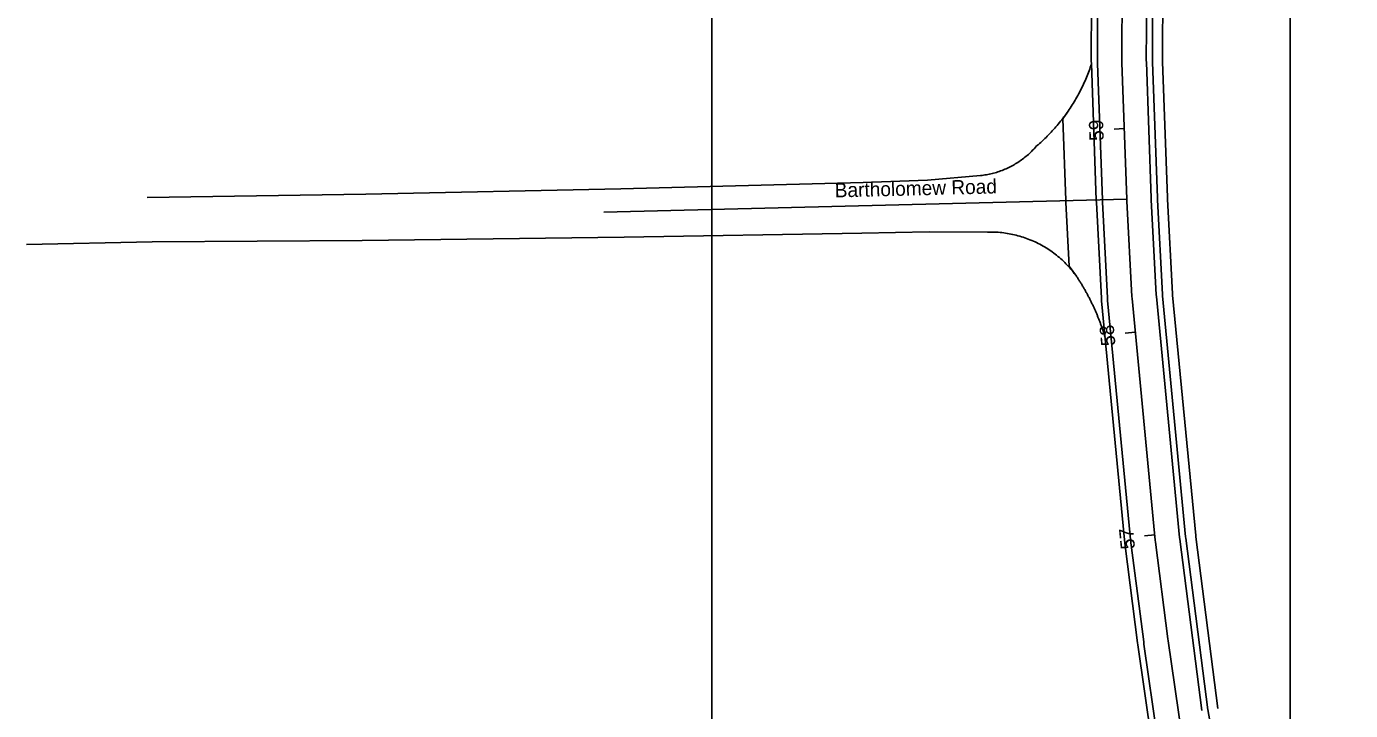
# Model space of a CAD drawing. Extents: x 2318076 to 2324211, y 613525 to 630327.
# Drawn here: x 2318076 to 2318726, y 620517 to 620852 of the extents above; entities that cross this region are included whole.
import ezdxf

# ---------------------------------------------------------------- set-up
doc = ezdxf.new("R2010")
doc.units = 0
for name, color, linetype in [('GE_P_CL_50', 7, 'Continuous'), ('GE_X_CL_50', 7, 'Continuous'), ('PV_P_EOP', 7, 'Continuous'), ('PV_P_Shoulder', 7, 'Continuous'), ('RD_X_GR_Rt', 7, 'Continuous'), ('RS_Raster1', 7, 'Continuous'), ('SC_Scratch3', 7, 'Continuous'), ('TX_P_1', 7, 'Continuous')]:
    doc.layers.add(name, color=color, linetype=linetype)

msp = doc.modelspace()

# ---------------------------------------------------------------- linework, layer by layer
at = {"layer": 'GE_P_CL_50'}
for p, q in [((2318615.25, 620802.3), (2318610.26, 620802.12)), ((2318620.66, 620702.47), (2318615.68, 620701.99)), ((2318630.24, 620602.93), (2318625.26, 620602.45))]:
    msp.add_line(p, q, dxfattribs=at)
msp.add_lwpolyline([(2318643.51, 620504.66), (2318636.81, 620551.04), (2318636.68, 620552.01), (2318630.59, 620599.46), (2318630.48, 620600.43), (2318619.07, 620719), (2318619.01, 620719.99), (2318616.54, 620766.75), (2318616.5, 620767.74), (2318614.09, 620834.59), (2318614.09, 620835.59), (2318614.08, 620836.59), (2318614.07, 620837.58), (2318614.09, 620849.48), (2318614.1, 620850.47), (2318614.18, 620857.38)], dxfattribs=at)
at = {"layer": 'GE_X_CL_50'}
msp.add_line((2318359.77, 620761.32), (2318616.5, 620767.74), dxfattribs=at)
at = {"layer": 'PV_P_EOP'}
for points in [[(2318631.64, 620502.89), (2318624.93, 620549.37), (2318624.78, 620550.44), (2318618.68, 620597.98), (2318618.54, 620599.14), (2318607.11, 620718.03), (2318607.03, 620719.28), (2318604.55, 620766.19), (2318604.51, 620767.29), (2318602.1, 620834.32), (2318602.09, 620835.48), (2318602.08, 620836.49), (2318602.07, 620837.55), (2318602.09, 620849.54), (2318602.1, 620850.59), (2318602.18, 620857.53)], [(2318653.3, 620516.78), (2318642.5, 620600.94), (2318642.41, 620601.72), (2318631.03, 620719.97), (2318630.99, 620720.7), (2318628.52, 620767.31), (2318628.49, 620768.2), (2318626.09, 620834.86), (2318626.08, 620835.69), (2318626.08, 620836.68), (2318626.07, 620837.62), (2318626.09, 620849.42), (2318626.1, 620850.35), (2318626.18, 620857.23)], [(2318599.11, 620833.88), (2318598.88, 620833.18), (2318598.59, 620832.34), (2318598.3, 620831.5), (2318597.99, 620830.66), (2318597.68, 620829.83), (2318597.36, 620828.99), (2318597.03, 620828.17), (2318596.69, 620827.34), (2318596.34, 620826.52), (2318595.99, 620825.7), (2318595.63, 620824.89), (2318595.25, 620824.08), (2318594.88, 620823.27), (2318594.49, 620822.47), (2318594.09, 620821.67), (2318593.69, 620820.87), (2318593.28, 620820.08), (2318592.86, 620819.29), (2318592.43, 620818.51), (2318592, 620817.73), (2318591.56, 620816.96), (2318591.11, 620816.19), (2318590.65, 620815.43), (2318590.18, 620814.67), (2318589.71, 620813.91), (2318589.23, 620813.16), (2318588.74, 620812.41), (2318588.24, 620811.67), (2318587.74, 620810.94), (2318585.07, 620807.12)], [(2318588.2, 620734.8), (2318586.55, 620766.05), (2318586.51, 620767.17), (2318585.07, 620807.12)], [(2318591.8, 620729.86), (2318588.2, 620734.8)], [(2318605.83, 620699.99), (2318605.72, 620700.35), (2318605.6, 620700.74), (2318605.48, 620701.12), (2318605.36, 620701.51), (2318605.24, 620701.89), (2318605.11, 620702.28), (2318604.99, 620702.66), (2318604.86, 620703.05), (2318604.73, 620703.43), (2318604.6, 620703.81), (2318604.47, 620704.2), (2318604.34, 620704.58), (2318604.21, 620704.96), (2318604.07, 620705.34), (2318603.94, 620705.72), (2318603.8, 620706.1), (2318603.66, 620706.48), (2318603.52, 620706.86), (2318603.38, 620707.24), (2318603.23, 620707.62), (2318603.09, 620707.99), (2318602.94, 620708.37), (2318602.8, 620708.75), (2318602.65, 620709.12), (2318602.5, 620709.5), (2318602.35, 620709.87), (2318602.19, 620710.25), (2318602.04, 620710.62), (2318601.89, 620711), (2318601.73, 620711.37), (2318601.57, 620711.74), (2318601.41, 620712.11), (2318601.25, 620712.48), (2318601.09, 620712.85), (2318600.93, 620713.22), (2318600.76, 620713.59), (2318600.6, 620713.96), (2318600.43, 620714.33), (2318600.26, 620714.7), (2318600.09, 620715.06), (2318599.92, 620715.43), (2318599.75, 620715.79), (2318599.57, 620716.16), (2318599.4, 620716.52), (2318599.22, 620716.89), (2318599.04, 620717.25), (2318598.86, 620717.61), (2318598.68, 620717.97), (2318598.5, 620718.34), (2318598.32, 620718.7), (2318598.14, 620719.06), (2318597.95, 620719.42), (2318597.76, 620719.77), (2318597.58, 620720.13), (2318597.39, 620720.49), (2318597.2, 620720.85), (2318597, 620721.2), (2318596.81, 620721.56), (2318596.62, 620721.91), (2318596.42, 620722.26), (2318596.22, 620722.62), (2318596.03, 620722.97), (2318595.83, 620723.32), (2318595.63, 620723.67), (2318595.42, 620724.02), (2318595.22, 620724.37), (2318595.02, 620724.72), (2318594.81, 620725.07), (2318594.6, 620725.42), (2318594.39, 620725.76), (2318594.19, 620726.11), (2318593.97, 620726.45), (2318593.76, 620726.8), (2318593.55, 620727.14), (2318593.33, 620727.48), (2318593.12, 620727.82), (2318592.9, 620728.17), (2318592.68, 620728.51), (2318592.47, 620728.85), (2318592.24, 620729.18), (2318592.02, 620729.52), (2318591.8, 620729.86)]]:
    msp.add_lwpolyline(points, dxfattribs=at)
at = {"layer": 'PV_P_Shoulder'}
for points in [[(2318628.67, 620502.45), (2318621.96, 620548.96), (2318621.81, 620550.04), (2318615.71, 620597.61), (2318615.56, 620598.82), (2318604.12, 620717.79), (2318604.03, 620719.11), (2318601.55, 620766.05), (2318601.51, 620767.17), (2318599.1, 620834.25), (2318599.09, 620835.45), (2318599.08, 620836.46), (2318599.07, 620837.54), (2318599.09, 620849.56), (2318599.1, 620850.62), (2318599.18, 620857.57)], [(2318656.27, 620517.16), (2318645.48, 620601.31), (2318645.39, 620602.05), (2318634.02, 620720.21), (2318633.98, 620720.88), (2318631.52, 620767.44), (2318631.49, 620768.31), (2318629.09, 620834.93), (2318629.08, 620835.72), (2318629.08, 620836.71), (2318629.07, 620837.63), (2318629.09, 620849.4), (2318629.1, 620850.32), (2318629.18, 620857.19)], [(2318726.31, 620118.23), (2318656.25, 620517.3)]]:
    msp.add_lwpolyline(points, dxfattribs=at)
at = {"layer": 'RD_X_GR_Rt'}
msp.add_lwpolyline([(2318661.23, 620517.8), (2318650.44, 620601.93), (2318650.36, 620602.58), (2318639.01, 620720.61), (2318638.97, 620721.17), (2318636.52, 620767.68), (2318636.48, 620768.5), (2318634.09, 620835.04), (2318634.08, 620835.77), (2318634.08, 620836.75), (2318634.07, 620837.64), (2318634.09, 620849.38), (2318634.1, 620850.27), (2318634.18, 620857.13)], dxfattribs=at)
at = {"layer": 'RS_Raster1'}
for p, q in [((2318544.73, 620779.28), (2318518.65, 620776.96)), ((2318369.82, 620749), (2318486.39, 620751.03)), ((2318486.39, 620751.03), (2318519.51, 620751.7)), ((2318548.09, 620751.54), (2318519.51, 620751.7))]:
    msp.add_line(p, q, dxfattribs=at)
for points in [[(2318599.11, 620833.88), (2318598.88, 620833.18), (2318598.59, 620832.34), (2318598.3, 620831.5), (2318597.99, 620830.66), (2318597.68, 620829.83), (2318597.36, 620828.99), (2318597.03, 620828.17), (2318596.69, 620827.34), (2318596.34, 620826.52), (2318595.99, 620825.7), (2318595.63, 620824.89), (2318595.25, 620824.08), (2318594.88, 620823.27), (2318594.49, 620822.47), (2318594.09, 620821.67), (2318593.69, 620820.87), (2318593.28, 620820.08), (2318592.86, 620819.29), (2318592.43, 620818.51), (2318592, 620817.73), (2318591.56, 620816.96), (2318591.11, 620816.19), (2318590.65, 620815.43), (2318590.18, 620814.67), (2318589.71, 620813.91), (2318589.23, 620813.16), (2318588.74, 620812.41), (2318588.24, 620811.67), (2318587.74, 620810.94), (2318587.23, 620810.21), (2318586.71, 620809.48), (2318586.19, 620808.76), (2318585.66, 620808.05), (2318585.12, 620807.34), (2318584.57, 620806.63), (2318584.02, 620805.94), (2318583.46, 620805.24), (2318582.89, 620804.56), (2318582.32, 620803.87), (2318581.74, 620803.2), (2318581.15, 620802.53), (2318580.55, 620801.87), (2318579.95, 620801.21), (2318579.35, 620800.56), (2318578.73, 620799.91), (2318578.11, 620799.27), (2318577.49, 620798.64), (2318576.85, 620798.01), (2318576.21, 620797.39), (2318575.57, 620796.78), (2318574.92, 620796.17), (2318574.26, 620795.57), (2318573.59, 620794.98), (2318572.93, 620794.39), (2318572.25, 620793.81)], [(2318572.25, 620793.81), (2318571.77, 620793.26), (2318571.29, 620792.72), (2318570.8, 620792.19), (2318570.29, 620791.67), (2318569.78, 620791.15), (2318569.26, 620790.65), (2318568.73, 620790.15), (2318568.2, 620789.67), (2318567.65, 620789.19), (2318567.1, 620788.72), (2318566.53, 620788.26), (2318565.96, 620787.81), (2318565.39, 620787.37), (2318564.8, 620786.95), (2318564.21, 620786.53), (2318563.61, 620786.12), (2318563.01, 620785.72), (2318562.39, 620785.33), (2318561.77, 620784.96), (2318561.15, 620784.59), (2318560.52, 620784.24), (2318559.88, 620783.89), (2318559.23, 620783.56), (2318558.58, 620783.24), (2318557.93, 620782.93), (2318557.27, 620782.63), (2318556.61, 620782.34), (2318555.94, 620782.07), (2318555.26, 620781.8), (2318554.58, 620781.55), (2318553.9, 620781.31), (2318553.21, 620781.08), (2318552.52, 620780.86), (2318551.83, 620780.66), (2318551.13, 620780.47), (2318550.43, 620780.28), (2318549.72, 620780.12), (2318549.02, 620779.96), (2318548.31, 620779.82), (2318547.6, 620779.68), (2318546.88, 620779.56), (2318546.17, 620779.46), (2318545.45, 620779.36), (2318544.73, 620779.28)], [(2318518.65, 620776.96), (2318487.18, 620775.88), (2318368.13, 620772.81)], [(2318591.8, 620729.86), (2318591.28, 620730.58), (2318590.74, 620731.29), (2318590.19, 620731.99), (2318589.63, 620732.69), (2318589.05, 620733.37), (2318588.47, 620734.04), (2318587.87, 620734.7), (2318587.27, 620735.36), (2318586.65, 620736), (2318586.02, 620736.63), (2318585.38, 620737.25), (2318584.73, 620737.86), (2318584.07, 620738.46), (2318583.4, 620739.04), (2318582.72, 620739.62), (2318582.02, 620740.18), (2318581.32, 620740.73), (2318580.61, 620741.27), (2318579.9, 620741.8), (2318579.17, 620742.31), (2318578.43, 620742.81), (2318577.69, 620743.3), (2318576.93, 620743.78), (2318576.17, 620744.24), (2318575.4, 620744.69), (2318574.62, 620745.13), (2318573.84, 620745.55), (2318573.05, 620745.96), (2318572.25, 620746.36), (2318571.45, 620746.74), (2318570.63, 620747.11), (2318569.82, 620747.46), (2318568.99, 620747.8), (2318568.16, 620748.13), (2318567.33, 620748.44), (2318566.49, 620748.74), (2318565.64, 620749.02), (2318564.79, 620749.29), (2318563.94, 620749.54), (2318563.08, 620749.78), (2318562.22, 620750), (2318561.35, 620750.21), (2318560.48, 620750.41), (2318559.61, 620750.59), (2318558.73, 620750.75), (2318557.86, 620750.9), (2318556.98, 620751.04), (2318556.09, 620751.15), (2318555.21, 620751.26), (2318554.32, 620751.35), (2318553.43, 620751.42), (2318552.54, 620751.48), (2318551.65, 620751.52), (2318550.76, 620751.55), (2318549.87, 620751.56), (2318548.98, 620751.56), (2318548.09, 620751.54)], [(2318605.83, 620699.99), (2318605.72, 620700.35), (2318605.6, 620700.74), (2318605.48, 620701.12), (2318605.36, 620701.51), (2318605.24, 620701.89), (2318605.11, 620702.28), (2318604.99, 620702.66), (2318604.86, 620703.05), (2318604.73, 620703.43), (2318604.6, 620703.81), (2318604.47, 620704.2), (2318604.34, 620704.58), (2318604.21, 620704.96), (2318604.07, 620705.34), (2318603.94, 620705.72), (2318603.8, 620706.1), (2318603.66, 620706.48), (2318603.52, 620706.86), (2318603.38, 620707.24), (2318603.23, 620707.62), (2318603.09, 620707.99), (2318602.94, 620708.37), (2318602.8, 620708.75), (2318602.65, 620709.12), (2318602.5, 620709.5), (2318602.35, 620709.87), (2318602.19, 620710.25), (2318602.04, 620710.62), (2318601.89, 620711), (2318601.73, 620711.37), (2318601.57, 620711.74), (2318601.41, 620712.11), (2318601.25, 620712.48), (2318601.09, 620712.85), (2318600.93, 620713.22), (2318600.76, 620713.59), (2318600.6, 620713.96), (2318600.43, 620714.33), (2318600.26, 620714.7), (2318600.09, 620715.06), (2318599.92, 620715.43), (2318599.75, 620715.79), (2318599.57, 620716.16), (2318599.4, 620716.52), (2318599.22, 620716.89), (2318599.04, 620717.25), (2318598.86, 620717.61), (2318598.68, 620717.97), (2318598.5, 620718.34), (2318598.32, 620718.7), (2318598.14, 620719.06), (2318597.95, 620719.42), (2318597.76, 620719.77), (2318597.58, 620720.13), (2318597.39, 620720.49), (2318597.2, 620720.85), (2318597, 620721.2), (2318596.81, 620721.56), (2318596.62, 620721.91), (2318596.42, 620722.26), (2318596.22, 620722.62), (2318596.03, 620722.97), (2318595.83, 620723.32), (2318595.63, 620723.67), (2318595.42, 620724.02), (2318595.22, 620724.37), (2318595.02, 620724.72), (2318594.81, 620725.07), (2318594.6, 620725.42), (2318594.39, 620725.76), (2318594.19, 620726.11), (2318593.97, 620726.45), (2318593.76, 620726.8), (2318593.55, 620727.14), (2318593.33, 620727.48), (2318593.12, 620727.82), (2318592.9, 620728.17), (2318592.68, 620728.51), (2318592.47, 620728.85), (2318592.24, 620729.18), (2318592.02, 620729.52), (2318591.8, 620729.86)]]:
    msp.add_lwpolyline(points, dxfattribs=at)
at = {"layer": 'SC_Scratch3'}
for p, q in [((2318412.82, 614778.41), (2318412.82, 630327.22)), ((2318696.66, 614778.41), (2318696.66, 630327.22))]:
    msp.add_line(p, q, dxfattribs=at)
at = {"layer": 'TX_P_1'}
for p, q in [((2318243.08, 620770.14), (2318135.63, 620768.53)), ((2318243.08, 620770.14), (2318368.13, 620772.81)), ((2318369.82, 620749), (2318241.25, 620747.36)), ((2318138.14, 620746.79), (2318076.45, 620745.46)), ((2318138.14, 620746.79), (2318241.25, 620747.36))]:
    msp.add_line(p, q, dxfattribs=at)

# ---------------------------------------------------------------- texts
at = {"layer": 'GE_P_CL_50'}
for s, rotation, p in [('59', 92.05824, (2318605.21, 620796.43)), ('Bartholomew Road', 1.43864, (2318473.24, 620768.54)), ('58', 95.49409, (2318610.98, 620695.97)), ('57', 95.49409, (2318620.58, 620596.23))]:
    msp.add_text(s, height=7, rotation=rotation, dxfattribs=at).set_placement(p)

doc.saveas('drawing.dxf')
